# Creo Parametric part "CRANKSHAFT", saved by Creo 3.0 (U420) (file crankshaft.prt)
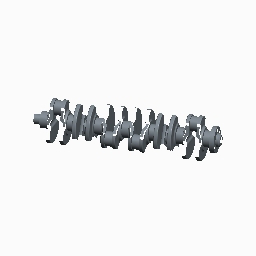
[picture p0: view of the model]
Units: millimeter Kilogram Sec (mmKs); MM, KILOGRAM, SECS

Created from: INLBS_PART_SOLID.PRT

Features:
  1. datum plane "RIGHT"
  2. datum plane "TOP"
  3. datum plane "FRONT"
  4. coordinate system
  5. group "LOCAL_GROUP_1"
  6. group "LOCAL_GROUP"
  7. sketch "Sketch 1"
  8. extrusion "Extrude 1"
  9. extruded cut "Extrude 2"
  10. hole "Hole 1"
  11. extrusion "Extrude 3"
  12. extruded cut "Extrude 4"
  13. round "Round 1"
  14. round "Round 2"
  15. round "Round 3"
  16. round "Round 4"
  17. round "Round 5"
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
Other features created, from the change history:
  hole "Hole 1"
  round "Round 6"
  round "Round 7"
  extrusion "Extrude 5"
  mirror "Mirror 1"
  group "COPIED_GROUP"
  sketch "Sketch 1 (2)"
  extrusion "Extrude 1 (2)"
  extruded cut "Extrude 2 (2)"
  hole "Hole 1 (2)"
  extrusion "Extrude 3 (2)"
  extruded cut "Extrude 4 (2)"
  round "Round 1 (2)"
  round "Round 2 (2)"
  round "Round 3 (2)"
  round "Round 4 (2)"
  round "Round 5 (2)"
  round "Round 6 (2)"
  round "Round 7 (2)"
  extrusion "Extrude 5 (2)"
  extrusion "Extrude 31"
  pattern "Pattern 1"
  extrusion "Extrude 31 [2]"
  extrusion "Extrude 31 [3]"
  extrusion "Extrude 31 [4]"
  extrusion "Extrude 31 [5]"
  extrusion "Extrude 31 [6]"
  extrusion "Extrude 31 [7]"
  extrusion "Extrude 32"
  extrusion "Extrude 33"
  extrusion "Extrude 34"
  chamfer "Chamfer 1"
  hole "Hole 7"
  pattern "Pattern 2"
  hole "Hole 7 [2]"
  hole "Hole 7 [3]"
  hole "Hole 7 [4]"
  hole "Hole 7 [5]"
  hole "Hole 7 [6]"
  datum axis "SHAFT"

Other named items: COPIED_GROUP_1, LOCAL_GROUP_2, LOCAL_GROUP_3, LOCAL_GROUP_4, COPIED_GROUP_2, LOCAL_GROUP_5, LOCAL_GROUP_6, LOCAL_GROUP_7, COPIED_GROUP_3, LOCAL_GROUP_8, LOCAL_GROUP_9, LOCAL_GROUP_10, COPIED_GROUP_4, LOCAL_GROUP_11, LOCAL_GROUP_12, LOCAL_GROUP_13, COPIED_GROUP_5, LOCAL_GROUP_14, LOCAL_GROUP_15, LOCAL_GROUP_16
